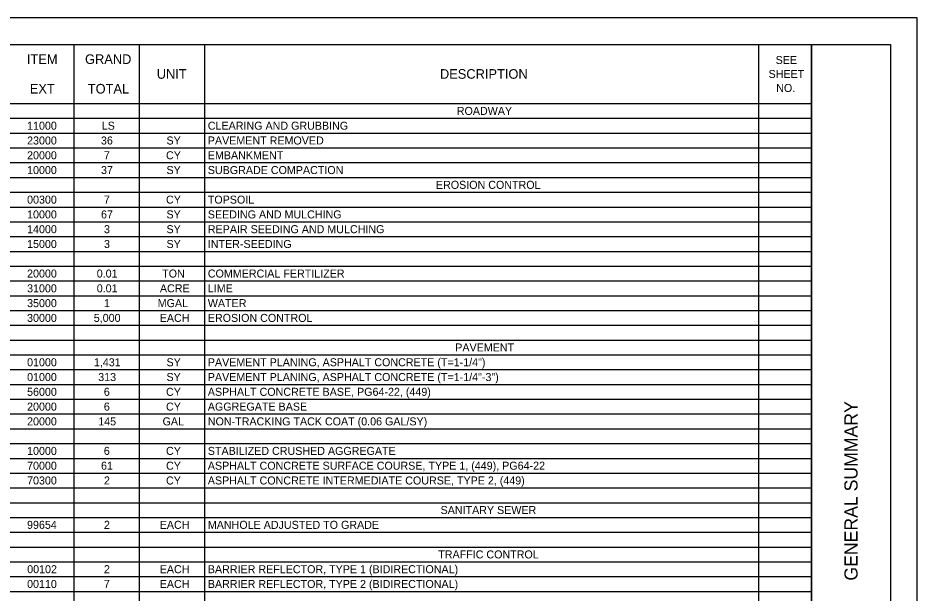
# Model space of a CAD drawing. Extents: x 0 to 34, y 0 to 22.
# Drawn here: x 16.98 to 34, y 11.11 to 22 of the extents above; entities that cross this region are included whole.
import ezdxf

# ---------------------------------------------------------------- set-up
doc = ezdxf.new("R2010")
doc.units = 0
for name, color, linetype in [('SH_Border', 7, 'Continuous'), ('SH_Cut_Line', 7, 'Continuous'), ('SH_Data', 7, 'Continuous'), ('SH_Text', 7, 'Continuous')]:
    doc.layers.add(name, color=color, linetype=linetype)

msp = doc.modelspace()

# ---------------------------------------------------------------- linework, layer by layer
at = {"layer": 'SH_Border'}
msp.add_line((32, 0.5), (32, 21.5), dxfattribs=at)
msp.add_lwpolyline([(1.5, 21.5), (33.5, 21.5), (33.5, 0.5), (1.5, 0.5)], close=True, dxfattribs=at)
at = {"layer": 'SH_Cut_Line'}
msp.add_lwpolyline([(0, 0), (34, 0), (34, 22), (0, 22)], close=True, dxfattribs=at)
at = {"layer": 'SH_Text'}
for p, q in [((1.5, 21.5), (32.002, 21.5)), ((18.036, 21.5), (18.036, 0.501)), ((19.271, 21.5), (19.271, 0.501)), ((20.506, 21.5), (20.506, 0.501)), ((30.998, 21.5), (30.998, 0.501)), ((32.002, 21.5), (32.002, 0.501)), ((1.5, 20.38), (32.002, 20.38)), ((1.5, 20.1), (32.002, 20.1)), ((1.5, 19.82), (32.002, 19.82)), ((1.5, 19.54), (32.002, 19.54)), ((1.5, 19.26), (32.002, 19.26)), ((1.5, 18.98), (32.002, 18.98)), ((1.5, 18.7), (32.002, 18.7)), ((1.5, 18.42), (32.002, 18.42)), ((1.5, 18.14), (32.002, 18.14)), ((1.5, 17.86), (32.002, 17.86)), ((1.5, 17.58), (32.002, 17.58)), ((1.5, 17.3), (32.002, 17.3)), ((1.5, 17.02), (32.002, 17.02)), ((1.5, 16.74), (32.002, 16.74)), ((1.5, 16.46), (32.002, 16.46)), ((1.5, 16.18), (32.002, 16.18)), ((1.5, 15.9), (32.002, 15.9)), ((1.5, 15.62), (32.002, 15.62)), ((1.5, 15.34), (32.002, 15.34)), ((1.5, 15.06), (32.002, 15.06)), ((1.5, 14.78), (32.002, 14.78)), ((1.5, 14.5), (32.002, 14.5)), ((1.5, 14.22), (32.002, 14.22)), ((1.5, 13.94), (32.002, 13.94)), ((1.5, 13.66), (32.002, 13.66)), ((1.5, 13.38), (32.002, 13.38)), ((1.5, 13.1), (32.002, 13.1)), ((1.5, 12.82), (32.002, 12.82)), ((1.5, 12.54), (32.002, 12.54)), ((1.5, 12.26), (32.002, 12.26)), ((1.5, 11.98), (32.002, 11.98)), ((1.5, 11.7), (32.002, 11.7)), ((1.5, 11.42), (32.002, 11.42)), ((1.5, 11.14), (32.002, 11.14))]:
    msp.add_line(p, q, dxfattribs=at)

# ---------------------------------------------------------------- texts
at = {"layer": 'SH_Data'}
msp.add_text('GENERAL SUMMARY', height=0.25, rotation=90, dxfattribs=at).set_placement((32.875, 11.344))
at = {"layer": 'SH_Text'}
for s, height, p in [('ITEM', 0.1818, (17.147, 21.129)), ('GRAND', 0.1818, (18.247, 21.129)), ('SEE ', 0.1515, (31.323, 21.129)), ('UNIT', 0.1818, (19.605, 20.849)), ('DESCRIPTION', 0.18183, (24.967, 20.849)), ('SHEET ', 0.1515, (31.189, 20.864)), ('EXT', 0.1818, (17.201, 20.569)), ('TOTAL', 0.1818, (18.299, 20.569)), ('NO.', 0.1515, (31.334, 20.599)), ('ROADWAY', 0.1515, (25.286, 20.164)), ('11000', 0.1515, (17.15, 19.884)), ('LS', 0.1515, (18.563, 19.884)), ('CLEARING AND GRUBBING', 0.15152, (20.572, 19.884)), ('23000', 0.1515, (17.15, 19.604)), ('36', 0.1515, (18.549, 19.604)), ('SY', 0.1515, (19.79, 19.604)), ('PAVEMENT REMOVED', 0.15152, (20.572, 19.604)), ('20000', 0.1515, (17.15, 19.324)), ('7', 0.152, (18.604, 19.324)), ('CY', 0.1515, (19.781, 19.324)), ('EMBANKMENT', 0.1515, (20.572, 19.324)), ('10000', 0.1515, (17.15, 19.044)), ('37', 0.1515, (18.55, 19.044)), ('SY', 0.1515, (19.79, 19.044)), ('SUBGRADE COMPACTION', 0.15152, (20.572, 19.044)), ('EROSION CONTROL', 0.15152, (24.891, 18.764)), ('00300', 0.1515, (17.15, 18.484)), ('7', 0.152, (18.604, 18.484)), ('CY', 0.1515, (19.781, 18.484)), ('TOPSOIL', 0.1515, (20.572, 18.484)), ('10000', 0.1515, (17.15, 18.204)), ('67', 0.1515, (18.55, 18.204)), ('SY', 0.1515, (19.79, 18.204)), ('SEEDING AND MULCHING', 0.15152, (20.572, 18.204)), ('14000', 0.1515, (17.15, 17.924)), ('3', 0.152, (18.606, 17.924)), ('SY', 0.1515, (19.79, 17.924)), ('REPAIR SEEDING AND MULCHING', 0.15152, (20.572, 17.924)), ('15000', 0.1515, (17.15, 17.644)), ('3', 0.152, (18.606, 17.644)), ('SY', 0.1515, (19.79, 17.644)), ('INTER-SEEDING', 0.15152, (20.572, 17.644)), ('20000', 0.1515, (17.15, 17.084)), ('0.01', 0.1515, (18.469, 17.084)), ('TON', 0.1515, (19.708, 17.084)), ('COMMERCIAL FERTILIZER', 0.15152, (20.572, 17.084)), ('31000', 0.1515, (17.15, 16.804)), ('0.01', 0.1515, (18.469, 16.804)), ('ACRE', 0.1515, (19.665, 16.804)), ('LIME', 0.1515, (20.572, 16.804)), ('35000', 0.1515, (17.15, 16.524)), ('1', 0.152, (18.605, 16.524)), ('MGAL', 0.1515, (19.623, 16.524)), ('WATER', 0.1515, (20.572, 16.524)), ('30000', 0.1515, (17.15, 16.244)), ('5,000', 0.1515, (18.413, 16.244)), ('EACH', 0.1515, (19.661, 16.244)), ('EROSION CONTROL', 0.15152, (20.572, 16.244)), ('PAVEMENT', 0.1515, (25.257, 15.684)), ('01000', 0.1515, (17.15, 15.404)), ('1,431', 0.1515, (18.415, 15.404)), ('SY', 0.1515, (19.79, 15.404)), ('PAVEMENT PLANING, ASPHALT CONCRETE (T=1-1/4")', 0.15152, (20.572, 15.404)), ('01000', 0.1515, (17.15, 15.124)), ('313', 0.1515, (18.497, 15.124)), ('SY', 0.1515, (19.79, 15.124)), ('PAVEMENT PLANING, ASPHALT CONCRETE (T=1-1/4"-3")', 0.15152, (20.572, 15.124)), ('56000', 0.1515, (17.15, 14.844)), ('6', 0.152, (18.603, 14.844)), ('CY', 0.1515, (19.781, 14.844)), ('ASPHALT CONCRETE BASE, PG64-22, (449)', 0.15152, (20.572, 14.844)), ('20000', 0.1515, (17.15, 14.564)), ('6', 0.152, (18.603, 14.564)), ('CY', 0.1515, (19.781, 14.564)), ('AGGREGATE BASE', 0.15152, (20.572, 14.564)), ('20000', 0.1515, (17.15, 14.284)), ('145', 0.1515, (18.497, 14.284)), ('GAL', 0.1515, (19.715, 14.284)), ('NON-TRACKING TACK COAT (0.06 GAL/SY)', 0.15152, (20.572, 14.284)), ('10000', 0.1515, (17.15, 13.725)), ('6', 0.152, (18.603, 13.725)), ('CY', 0.1515, (19.781, 13.725)), ('STABILIZED CRUSHED AGGREGATE', 0.15152, (20.572, 13.725)), ('70000', 0.1515, (17.15, 13.445)), ('61', 0.1515, (18.55, 13.445)), ('CY', 0.1515, (19.781, 13.445)), ('ASPHALT CONCRETE SURFACE COURSE, TYPE 1, (449), PG64-22', 0.15152, (20.572, 13.445)), ('70300', 0.1515, (17.15, 13.165)), ('2', 0.152, (18.605, 13.165)), ('CY', 0.1515, (19.781, 13.165)), ('ASPHALT CONCRETE INTERMEDIATE COURSE, TYPE 2, (449)', 0.15152, (20.572, 13.165)), ('SANITARY SEWER', 0.15152, (24.979, 12.605)), ('99654', 0.1515, (17.149, 12.325)), ('2', 0.152, (18.605, 12.325)), ('EACH', 0.1515, (19.661, 12.325)), ('MANHOLE ADJUSTED TO GRADE', 0.15152, (20.572, 12.325)), ('TRAFFIC CONTROL', 0.15152, (24.935, 11.765)), ('00102', 0.1515, (17.152, 11.485)), ('2', 0.152, (18.605, 11.485)), ('EACH', 0.1515, (19.661, 11.485)), ('BARRIER REFLECTOR, TYPE 1 (BIDIRECTIONAL)', 0.15152, (20.572, 11.485)), ('00110', 0.1515, (17.15, 11.205)), ('7', 0.152, (18.604, 11.205)), ('EACH', 0.1515, (19.661, 11.205)), ('BARRIER REFLECTOR, TYPE 2 (BIDIRECTIONAL)', 0.15152, (20.572, 11.205))]:
    msp.add_text(s, height=height, dxfattribs=at).set_placement(p)

doc.saveas('drawing.dxf')
